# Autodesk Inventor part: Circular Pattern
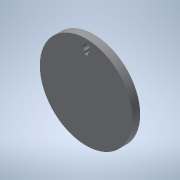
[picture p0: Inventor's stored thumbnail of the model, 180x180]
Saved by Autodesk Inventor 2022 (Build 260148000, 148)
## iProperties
Created: 2013-12
Part Number: Circular Pattern
Material: Generic
Document SubType Name: Modeling
Designer: John
Density: 1 g/cm^3
Appearance: Default
Author: John
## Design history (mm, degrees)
sketch "Sketch1"
  geometry: C1 r 38.1 at (0, 0); 1 further point
  constraints: 1 centre point, 1 coincident
  dimensions: "d0" = 76.2 diameter of C1
extrude "Extrusion1" new body sketch "Sketch1" distance "d1" = 6.35; taper "d2" = 0 deg
sketch "Sketch2"
  geometry: C1 r 38.1 at (0, 0) reference; C2 r 3.175 at (0, 31.75)
  constraints: 1 centre point, 1 vertical alignment
  dimensions: "d3" = 6.35 diameter of C2; "d6" = 31.75 distance of C1.centre C2.centre
extrude "Extrusion2" cut sketch "Sketch2" extent not by distance; stored distance "d7" = 12.7; taper "d8" = 0 deg
sketch "Sketch3"
  geometry: L1 (0, 31.75)-(1.27, 31.75); L2 (1.27, 31.75)-(1.27, 26.67); L3 (1.27, 26.67)-(0, 26.67); L4 (0, 26.67)-(0, 31.75); L5 (0, 31.75)-(-1.27, 31.75); L6 (-1.27, 31.75)-(-1.27, 26.67); L7 (-1.27, 26.67)-(0, 26.67); L8 (0, 26.67)-(0, 31.75); C1 r 3.175 at (0, 31.75) reference
  constraints: 16 end point, 4 parallel, 2 equal length, 2 horizontal, 2 perpendicular
  dimensions: "d9" = 1.27 distance of L2.end L3.end; "d10" = 5.08 distance of L1.end L2.end
extrude "Extrusion3" cut sketch "Sketch3" extent not by distance; stored distance "d11" = 25.4; taper "d12" = 0 deg
body "Solid1"
